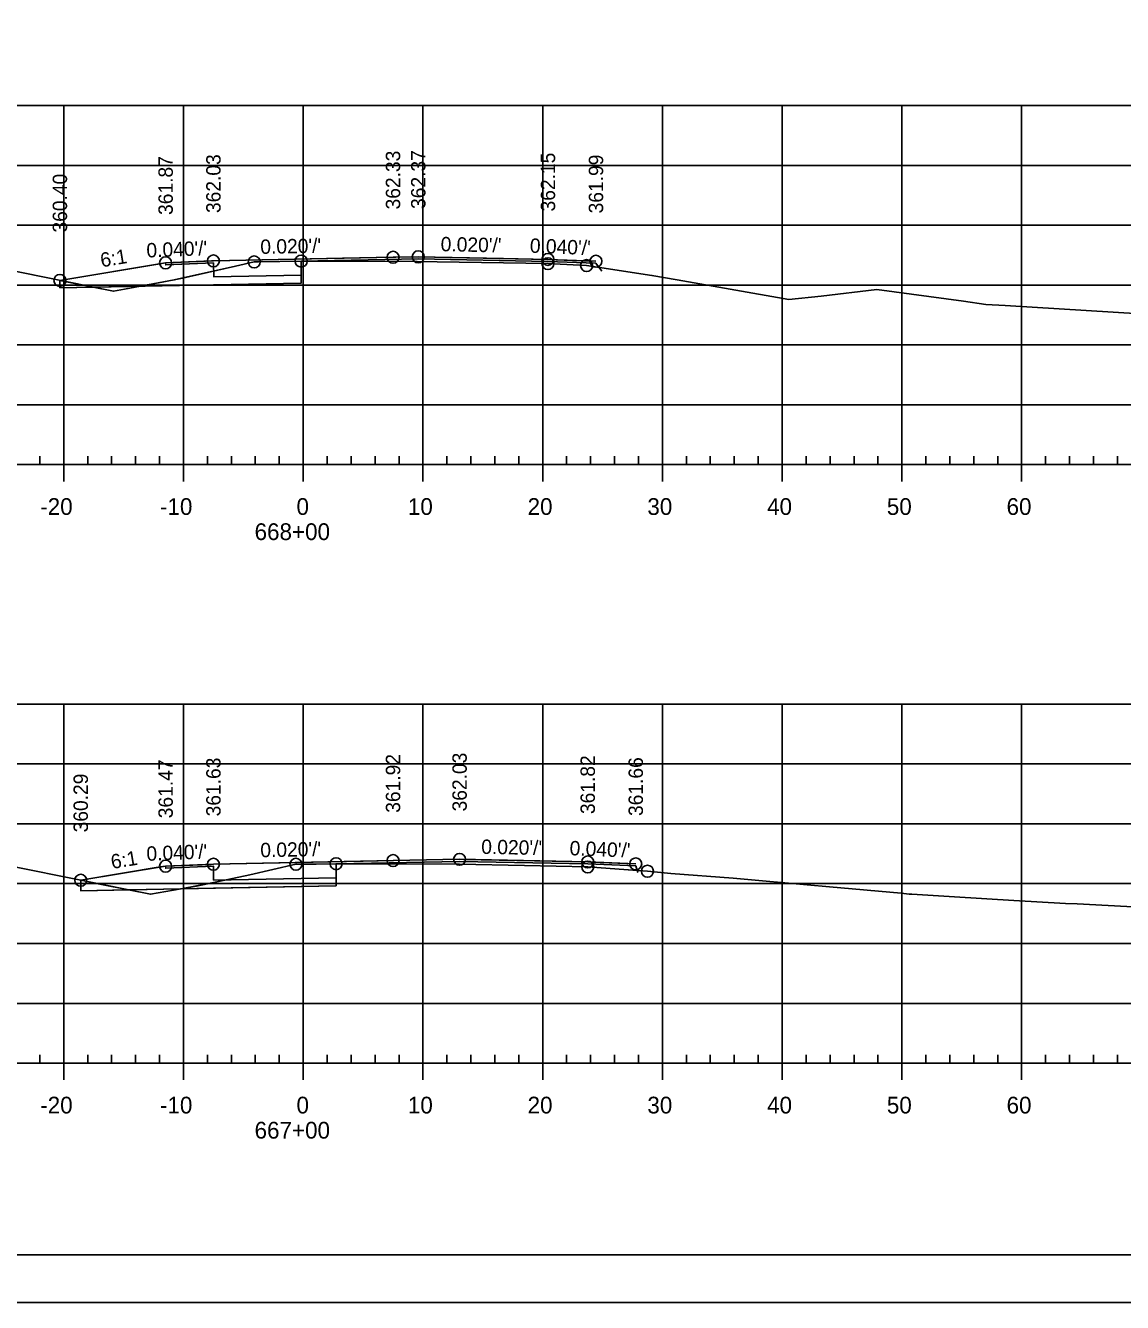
# Model space of a CAD drawing. Extents: x 1359801 to 1362404, y 372415 to 374228.
# Drawn here: x 1359948.2 to 1360039.8, y 373588 to 373694.6 of the extents above; entities that cross this region are included whole.
import ezdxf

# ---------------------------------------------------------------- set-up
doc = ezdxf.new("R2010")
doc.units = 0
for name, color, linetype in [('S_DRG_PT_SYM', 7, 'Continuous'), ('S_ELECTRIC_UTILITIES_ANNOT', 7, 'Continuous'), ('S_IRON_PIN', 7, 'Continuous'), ('S_MAILBOX', 7, 'Continuous'), ('S_PRIMARY_CTL', 7, 'Continuous'), ('S_SANITARY_SEWER', 7, 'Continuous'), ('S_SHOULDER', 7, 'Continuous'), ('S_UNDERGROUND_CABLE', 7, 'Continuous'), ('S_UTL_PT_SYM', 7, 'Continuous'), ('S_WATER_UTILITIES', 7, 'Continuous')]:
    doc.layers.add(name, color=color, linetype=linetype)

msp = doc.modelspace()

# ---------------------------------------------------------------- linework, layer by layer
at = {"layer": 'S_DRG_PT_SYM'}
for points in [[(1359945.88, 373674.39), (1359955.5, 373672.42), (1359956.43, 373672.6), (1359960.58, 373673.37), (1359965.7, 373674.53), (1359967.26, 373674.87), (1359967.62, 373674.87), (1359971.18, 373674.94), (1359972.21, 373674.94), (1359980.86, 373674.91), (1359982.55, 373674.89), (1359991.79, 373674.73), (1359992.25, 373674.71), (1359995.02, 373674.57), (1359995.93, 373674.43), (1360000.47, 373673.75), (1360002.57, 373673.38), (1360011.91, 373671.74), (1360014.6, 373672.02), (1360019.26, 373672.57), (1360026.5, 373671.61), (1360028.35, 373671.32), (1360029.96, 373671.24), (1360045.75, 373670.25)], [(1359946.96, 373624.4), (1359958.6, 373622.05), (1359962.44, 373622.74), (1359966.89, 373623.67), (1359970.74, 373624.56), (1359972.44, 373624.58), (1359974.1, 373624.6), (1359979.51, 373624.59), (1359984.4, 373624.58), (1359989.82, 373624.45), (1359995.11, 373624.33), (1359997.74, 373624.14), (1360000.1, 373623.98), (1360002.06, 373623.79), (1360007.25, 373623.39), (1360009.71, 373623.17), (1360015.31, 373622.68), (1360021.3, 373622.15), (1360021.95, 373622.07), (1360022.03, 373622.07), (1360022.19, 373622.06), (1360025.74, 373621.85), (1360030.7, 373621.53), (1360035.02, 373621.27), (1360035.98, 373621.24), (1360046.87, 373620.68)]]:
    msp.add_lwpolyline(points, dxfattribs=at)
at = {"layer": 'S_ELECTRIC_UTILITIES_ANNOT'}
for p, q in [((1359995.8, 373674.76), (1359991.79, 373674.92)), ((1359995.8, 373674.76), (1359996.29, 373674.09)), ((1359996.05, 373674.41), (1359995.8, 373674.76)), ((1359951.03, 373673.33), (1359951.03, 373672.71)), ((1359953.81, 373672.76), (1359951.03, 373673.33)), ((1359951.03, 373673.33), (1359951.03, 373673.33)), ((1359951.03, 373672.71), (1359953.81, 373672.76)), ((1359957.72, 373672.84), (1359953.81, 373672.76)), ((1359957.72, 373672.84), (1359963.85, 373672.96)), ((1359974.1, 373623.26), (1359974.1, 373624.6)), ((1359999.12, 373624.43), (1359995.11, 373624.59)), ((1359999.12, 373624.43), (1359999.3, 373623.87)), ((1359999.25, 373624.04), (1359999.12, 373624.43)), ((1359952.77, 373623.22), (1359952.77, 373622.84)), ((1359952.79, 373623.22), (1359952.77, 373623.22)), ((1359954.51, 373622.88), (1359952.79, 373623.22)), ((1359956.76, 373622.42), (1359956.76, 373622.42)), ((1359956.76, 373622.42), (1359956.76, 373622.42))]:
    msp.add_line(p, q, dxfattribs=at)
for points in [[(1359971.18, 373674.94), (1359967.62, 373674.87), (1359967.26, 373674.87), (1359965.7, 373674.53), (1359961.28, 373673.53), (1359959.57, 373673.19), (1359957.72, 373672.84)], [(1359963.85, 373672.96), (1359971.18, 373673.11), (1359971.18, 373674.94)], [(1359991.79, 373674.92), (1359980.96, 373675.14), (1359971.18, 373674.94)], [(1359971.18, 373674.94), (1359972.21, 373674.94), (1359980.86, 373674.91), (1359982.55, 373674.89), (1359991.79, 373674.73), (1359992.25, 373674.71), (1359995.02, 373674.57), (1359995.93, 373674.43), (1359996.05, 373674.41)], [(1359953.81, 373672.76), (1359955.5, 373672.42), (1359956.43, 373672.6), (1359957.72, 373672.84), (1359957.72, 373672.84)], [(1359974.1, 373624.6), (1359972.44, 373624.58), (1359970.74, 373624.56), (1359966.89, 373623.67), (1359964.01, 373623.06)], [(1359995.11, 373624.59), (1359984.41, 373624.8), (1359974.1, 373624.6)], [(1359974.1, 373624.6), (1359979.51, 373624.59), (1359984.4, 373624.58), (1359989.82, 373624.45), (1359995.11, 373624.33), (1359997.74, 373624.14), (1359999.25, 373624.04)], [(1359952.77, 373622.84), (1359952.77, 373622.34), (1359956.76, 373622.42), (1359954.51, 373622.88)], [(1359956.76, 373622.42), (1359958.6, 373622.05), (1359961.15, 373622.51), (1359956.76, 373622.42)], [(1359964.01, 373623.06), (1359961.15, 373622.51), (1359974.1, 373622.76), (1359974.1, 373623.26)]]:
    msp.add_lwpolyline(points, dxfattribs=at)
at = {"layer": 'S_MAILBOX'}
for p, q in [((1359826.35, 373687.94), (1360116.35, 373687.94)), ((1359951.35, 373657.94), (1359951.35, 373687.94)), ((1359961.35, 373657.94), (1359961.35, 373687.94)), ((1359971.35, 373657.94), (1359971.35, 373687.94)), ((1359981.35, 373657.94), (1359981.35, 373687.94)), ((1359991.35, 373657.94), (1359991.35, 373687.94)), ((1360001.35, 373657.94), (1360001.35, 373687.94)), ((1360011.35, 373657.94), (1360011.35, 373687.94)), ((1360021.35, 373657.94), (1360021.35, 373687.94)), ((1360031.35, 373657.94), (1360031.35, 373687.94)), ((1359826.35, 373682.94), (1360116.35, 373682.94)), ((1359826.35, 373677.94), (1360116.35, 373677.94)), ((1359826.35, 373672.94), (1360116.35, 373672.94)), ((1359826.35, 373667.94), (1360116.35, 373667.94)), ((1359826.35, 373662.94), (1360116.35, 373662.94)), ((1359826.35, 373657.94), (1360116.35, 373657.94)), ((1359826.35, 373637.94), (1360116.35, 373637.94)), ((1359951.35, 373607.94), (1359951.35, 373637.94)), ((1359961.35, 373607.94), (1359961.35, 373637.94)), ((1359971.35, 373607.94), (1359971.35, 373637.94)), ((1359981.35, 373607.94), (1359981.35, 373637.94)), ((1359991.35, 373607.94), (1359991.35, 373637.94)), ((1360001.35, 373607.94), (1360001.35, 373637.94)), ((1360011.35, 373607.94), (1360011.35, 373637.94)), ((1360021.35, 373607.94), (1360021.35, 373637.94)), ((1360031.35, 373607.94), (1360031.35, 373637.94)), ((1359826.35, 373632.94), (1360116.35, 373632.94)), ((1359826.35, 373627.94), (1360116.35, 373627.94)), ((1359826.35, 373622.94), (1360116.35, 373622.94)), ((1359826.35, 373617.94), (1360116.35, 373617.94)), ((1359826.35, 373612.94), (1360116.35, 373612.94)), ((1359826.35, 373607.94), (1360116.35, 373607.94))]:
    msp.add_line(p, q, dxfattribs=at)
at = {"layer": 'S_SANITARY_SEWER'}
for points in [[(1359951.03, 373673.33), (1359959.39, 373674.72), (1359959.86, 373674.8), (1359963.7, 373674.96), (1359963.85, 373674.96), (1359974.64, 373675.18), (1359978.85, 373675.26), (1359979.09, 373675.27), (1359980.96, 373675.3), (1359988.09, 373675.16), (1359991.79, 373675.09), (1359993.84, 373675), (1359995.8, 373674.93)], [(1359959.86, 373674.8), (1359963.85, 373674.96), (1359978.85, 373675.26), (1359980.96, 373675.3), (1359991.79, 373675.09), (1359995.8, 373674.93)], [(1359952.77, 373623.22), (1359959.41, 373624.33), (1359959.86, 373624.4), (1359963.67, 373624.55), (1359963.85, 373624.56), (1359976.37, 373624.81), (1359978.85, 373624.86), (1359978.9, 373624.86), (1359984.41, 373624.97), (1359984.75, 373624.96), (1359995.11, 373624.75), (1359995.4, 373624.74), (1359999.12, 373624.59)], [(1359959.86, 373624.4), (1359963.85, 373624.56), (1359978.85, 373624.86), (1359984.41, 373624.97), (1359995.11, 373624.75), (1359999.12, 373624.59)]]:
    msp.add_lwpolyline(points, dxfattribs=at)
at = {"layer": 'S_SHOULDER'}
for p, q in [((1359951.03, 373672.71), (1359951.03, 373673.33)), ((1359963.86, 373624.39), (1359963.86, 373623.23)), ((1359952.77, 373622.34), (1359952.77, 373623.22)), ((1359800.95, 373587.96), (1360134.28, 373587.96))]:
    msp.add_line(p, q, dxfattribs=at)
for points in [[(1359800.94, 373801.29), (1360134.28, 373801.29), (1360134.28, 373587.95), (1359800.94, 373587.95)], [(1360047.27, 373797.4), (1360047.27, 373787.52), (1360083, 373787.52), (1360083, 373784.6), (1360106.2, 373784.6), (1360106.2, 373760.26), (1360129.53, 373760.26), (1360129.53, 373591.94), (1359813.35, 373591.94), (1359813.35, 373797.4)]]:
    msp.add_lwpolyline(points, close=True, dxfattribs=at)
for points in [[(1359951.03, 373673.33), (1359959.86, 373674.8), (1359959.87, 373674.63), (1359963.86, 373674.79)], [(1359959.86, 373674.63), (1359963.86, 373674.79)], [(1359963.86, 373674.79), (1359963.88, 373673.63), (1359971.18, 373673.78)], [(1359971.18, 373673.78), (1359971.18, 373673.11), (1359963.85, 373672.96), (1359951.03, 373672.71)], [(1359952.77, 373623.22), (1359959.86, 373624.4), (1359959.87, 373624.23), (1359963.86, 373624.39), (1359963.86, 373623.23), (1359974.1, 373623.43)], [(1359974.1, 373623.43), (1359974.1, 373622.76), (1359963.85, 373622.56), (1359952.77, 373622.34)]]:
    msp.add_lwpolyline(points, dxfattribs=at)
for centre in [(1359978.85, 373675.26), (1359980.96, 373675.3), (1359959.86, 373674.8), (1359963.85, 373674.96), (1359967.26, 373674.87), (1359971.18, 373674.94), (1359991.79, 373675.09), (1359991.79, 373674.73), (1359995.02, 373674.57), (1359995.8, 373674.93), (1359951.03, 373673.33), (1359959.86, 373624.4), (1359963.85, 373624.56), (1359970.74, 373624.56), (1359974.1, 373624.6), (1359978.85, 373624.86), (1359984.41, 373624.97), (1359995.11, 373624.75), (1359995.11, 373624.33), (1359999.12, 373624.59), (1359952.77, 373623.22), (1360000.1, 373623.98)]:
    msp.add_circle(centre, 0.5, dxfattribs=at)
at = {"layer": 'S_UNDERGROUND_CABLE'}
for p, q in [((1359951.03, 373673.33), (1359951.03, 373672.71)), ((1359952.77, 373623.22), (1359952.77, 373622.34))]:
    msp.add_line(p, q, dxfattribs=at)
for points in [[(1359951.03, 373672.71), (1359963.85, 373672.96), (1359971.18, 373673.11), (1359971.18, 373674.94), (1359980.96, 373675.14), (1359991.79, 373674.92), (1359995.8, 373674.76)], [(1359952.77, 373622.34), (1359963.85, 373622.56), (1359974.1, 373622.76), (1359974.1, 373624.6), (1359984.41, 373624.8), (1359995.11, 373624.59), (1359999.12, 373624.43)]]:
    msp.add_lwpolyline(points, dxfattribs=at)
at = {"layer": 'S_UTL_PT_SYM'}
msp.add_line((1360129.53, 373591.94), (1359813.35, 373591.94), dxfattribs=at)
at = {"layer": 'S_WATER_UTILITIES'}
for p, q in [((1359826.35, 373657.94), (1360116.35, 373657.94)), ((1359949.35, 373657.94), (1359949.35, 373658.64)), ((1359951.35, 373656.54), (1359951.35, 373657.94)), ((1359953.35, 373657.94), (1359953.35, 373658.64)), ((1359955.35, 373657.94), (1359955.35, 373658.64)), ((1359957.35, 373657.94), (1359957.35, 373658.64)), ((1359959.35, 373657.94), (1359959.35, 373658.64)), ((1359961.35, 373656.54), (1359961.35, 373657.94)), ((1359963.35, 373657.94), (1359963.35, 373658.64)), ((1359965.35, 373657.94), (1359965.35, 373658.64)), ((1359967.35, 373657.94), (1359967.35, 373658.64)), ((1359969.35, 373657.94), (1359969.35, 373658.64)), ((1359971.35, 373656.54), (1359971.35, 373657.94)), ((1359973.35, 373657.94), (1359973.35, 373658.64)), ((1359975.35, 373657.94), (1359975.35, 373658.64)), ((1359977.35, 373657.94), (1359977.35, 373658.64)), ((1359979.35, 373657.94), (1359979.35, 373658.64)), ((1359981.35, 373656.54), (1359981.35, 373657.94)), ((1359983.35, 373657.94), (1359983.35, 373658.64)), ((1359985.35, 373657.94), (1359985.35, 373658.64)), ((1359987.35, 373657.94), (1359987.35, 373658.64)), ((1359989.35, 373657.94), (1359989.35, 373658.64)), ((1359991.35, 373656.54), (1359991.35, 373657.94)), ((1359993.35, 373657.94), (1359993.35, 373658.64)), ((1359995.35, 373657.94), (1359995.35, 373658.64)), ((1359997.35, 373657.94), (1359997.35, 373658.64)), ((1359999.35, 373657.94), (1359999.35, 373658.64)), ((1360001.35, 373656.54), (1360001.35, 373657.94)), ((1360003.35, 373657.94), (1360003.35, 373658.64)), ((1360005.35, 373657.94), (1360005.35, 373658.64)), ((1360007.35, 373657.94), (1360007.35, 373658.64)), ((1360009.35, 373657.94), (1360009.35, 373658.64)), ((1360011.35, 373656.54), (1360011.35, 373657.94)), ((1360013.35, 373657.94), (1360013.35, 373658.64)), ((1360015.35, 373657.94), (1360015.35, 373658.64)), ((1360017.35, 373657.94), (1360017.35, 373658.64)), ((1360019.35, 373657.94), (1360019.35, 373658.64)), ((1360021.35, 373656.54), (1360021.35, 373657.94)), ((1360023.35, 373657.94), (1360023.35, 373658.64)), ((1360025.35, 373657.94), (1360025.35, 373658.64)), ((1360027.35, 373657.94), (1360027.35, 373658.64)), ((1360029.35, 373657.94), (1360029.35, 373658.64)), ((1360031.35, 373656.54), (1360031.35, 373657.94)), ((1360033.35, 373657.94), (1360033.35, 373658.64)), ((1360035.35, 373657.94), (1360035.35, 373658.64)), ((1360037.35, 373657.94), (1360037.35, 373658.64)), ((1360039.35, 373657.94), (1360039.35, 373658.64)), ((1359949.35, 373607.94), (1359949.35, 373608.64)), ((1359953.35, 373607.94), (1359953.35, 373608.64)), ((1359955.35, 373607.94), (1359955.35, 373608.64)), ((1359957.35, 373607.94), (1359957.35, 373608.64)), ((1359959.35, 373607.94), (1359959.35, 373608.64)), ((1359963.35, 373607.94), (1359963.35, 373608.64)), ((1359965.35, 373607.94), (1359965.35, 373608.64)), ((1359967.35, 373607.94), (1359967.35, 373608.64)), ((1359969.35, 373607.94), (1359969.35, 373608.64)), ((1359973.35, 373607.94), (1359973.35, 373608.64)), ((1359975.35, 373607.94), (1359975.35, 373608.64)), ((1359977.35, 373607.94), (1359977.35, 373608.64)), ((1359979.35, 373607.94), (1359979.35, 373608.64)), ((1359983.35, 373607.94), (1359983.35, 373608.64)), ((1359985.35, 373607.94), (1359985.35, 373608.64)), ((1359987.35, 373607.94), (1359987.35, 373608.64)), ((1359989.35, 373607.94), (1359989.35, 373608.64)), ((1359993.35, 373607.94), (1359993.35, 373608.64)), ((1359995.35, 373607.94), (1359995.35, 373608.64)), ((1359997.35, 373607.94), (1359997.35, 373608.64)), ((1359999.35, 373607.94), (1359999.35, 373608.64)), ((1360003.35, 373607.94), (1360003.35, 373608.64)), ((1360005.35, 373607.94), (1360005.35, 373608.64)), ((1360007.35, 373607.94), (1360007.35, 373608.64)), ((1360009.35, 373607.94), (1360009.35, 373608.64)), ((1360013.35, 373607.94), (1360013.35, 373608.64)), ((1360015.35, 373607.94), (1360015.35, 373608.64)), ((1360017.35, 373607.94), (1360017.35, 373608.64)), ((1360019.35, 373607.94), (1360019.35, 373608.64)), ((1360023.35, 373607.94), (1360023.35, 373608.64)), ((1360025.35, 373607.94), (1360025.35, 373608.64)), ((1360027.35, 373607.94), (1360027.35, 373608.64)), ((1360029.35, 373607.94), (1360029.35, 373608.64)), ((1360033.35, 373607.94), (1360033.35, 373608.64)), ((1360035.35, 373607.94), (1360035.35, 373608.64)), ((1360037.35, 373607.94), (1360037.35, 373608.64)), ((1360039.35, 373607.94), (1360039.35, 373608.64)), ((1359826.35, 373607.94), (1360116.35, 373607.94)), ((1359951.35, 373606.54), (1359951.35, 373607.94)), ((1359961.35, 373606.54), (1359961.35, 373607.94)), ((1359971.35, 373606.54), (1359971.35, 373607.94)), ((1359981.35, 373606.54), (1359981.35, 373607.94)), ((1359991.35, 373606.54), (1359991.35, 373607.94)), ((1360001.35, 373606.54), (1360001.35, 373607.94)), ((1360011.35, 373606.54), (1360011.35, 373607.94)), ((1360021.35, 373606.54), (1360021.35, 373607.94)), ((1360031.35, 373606.54), (1360031.35, 373607.94))]:
    msp.add_line(p, q, dxfattribs=at)

# ---------------------------------------------------------------- texts
at = {"layer": 'S_IRON_PIN'}
for s, rotation, p in [('361.87', 90, (1359960.46, 373678.8)), ('362.03', 90, (1359964.45, 373678.96)), ('362.33', 90, (1359979.45, 373679.26)), ('362.37', 90, (1359981.56, 373679.3)), ('362.15', 90, (1359992.39, 373679.09)), ('361.99', 90, (1359996.4, 373678.93)), ('360.40', 90, (1359951.63, 373677.33)), ("0.020'/'", 1.1432, (1359967.78, 373675.54)), ("0.020'/'", 358.853, (1359982.82, 373675.77)), ("0.040'/'", 357.709, (1359990.26, 373675.65)), ('6:1', 9.4647, (1359954.51, 373674.42)), ("0.040'/'", 2.2887, (1359958.28, 373675.24)), ('361.47', 90, (1359960.46, 373628.4)), ('361.63', 90, (1359964.45, 373628.56)), ('361.92', 90, (1359979.45, 373628.86)), ('362.03', 90, (1359985.01, 373628.97)), ('361.82', 90, (1359995.71, 373628.75)), ('361.66', 90, (1359999.72, 373628.59)), ('360.29', 90, (1359953.37, 373627.22)), ('6:1', 9.4572, (1359955.39, 373624.16)), ("0.040'/'", 2.2811, (1359958.28, 373624.84)), ("0.020'/'", 1.1355, (1359967.78, 373625.14)), ("0.020'/'", 358.8454, (1359986.21, 373625.43)), ("0.040'/'", 357.7009, (1359993.58, 373625.32))]:
    msp.add_text(s, height=1.2, rotation=rotation, dxfattribs=at).set_placement(p)
at = {"layer": 'S_PRIMARY_CTL'}
for s, p in [('-20', (1359949.39, 373653.74)), ('-10', (1359959.39, 373653.74)), ('0', (1359970.79, 373653.74)), ('10', (1359980.09, 373653.74)), ('20', (1359990.09, 373653.74)), ('30', (1360000.09, 373653.74)), ('40', (1360010.09, 373653.74)), ('50', (1360020.09, 373653.74)), ('60', (1360030.09, 373653.74)), ('668+00', (1359967.29, 373651.64)), ('-20', (1359949.39, 373603.74)), ('-10', (1359959.39, 373603.74)), ('0', (1359970.79, 373603.74)), ('10', (1359980.09, 373603.74)), ('20', (1359990.09, 373603.74)), ('30', (1360000.09, 373603.74)), ('40', (1360010.09, 373603.74)), ('50', (1360020.09, 373603.74)), ('60', (1360030.09, 373603.74)), ('667+00', (1359967.29, 373601.64))]:
    msp.add_text(s, height=1.4, dxfattribs=at).set_placement(p)

doc.saveas('drawing.dxf')
